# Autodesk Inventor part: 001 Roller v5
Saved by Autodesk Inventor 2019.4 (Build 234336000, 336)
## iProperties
Created: 2020-06
Part Number: 001 Roller v5
Material: Generic
Document SubType Name: Modeling
Designer: Administrator
Density: 1 g/cm^3
Appearance: Default
Title: 001 Roller v5
Author: Administrator
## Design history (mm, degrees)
feature "Roller"
body "Solid1"
